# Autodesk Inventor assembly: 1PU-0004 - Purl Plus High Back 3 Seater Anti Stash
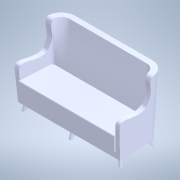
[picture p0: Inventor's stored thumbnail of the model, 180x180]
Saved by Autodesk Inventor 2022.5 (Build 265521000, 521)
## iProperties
Created: 2025-09
Part Number: 1PU-0004 - Purl Plus High Back 3 Seater Anti Stash
Description: STEP AP214
Document SubType Name: Assembly
Designer: Mark.Glazzard
Title: 1PU-0004 - Purl Plus High Back 3 Seater Anti Stash (UPHOLSTERED).STEP
Revision Number: ANY
Sending System: SolidWorks 2025
Preprocessor: SwSTEP 2.0
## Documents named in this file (5)
- S:\DRAWINGS\DRAWING OFFICE ONLY\WIP\1306 Purl 3-Seater\1PU-0004 - Purl Plus High Back 3-Seater Anti-Stash\1PU-0004 - SIMPLIFIED\1PU-0004 - Purl Plus High Back 3 Seater Anti Stash.iam
- S:\DRAWINGS\DRAWING OFFICE ONLY\WIP\1306 Purl 3-Seater\1PU-0004 - Purl Plus High Back 3-Seater Anti-Stash\1PU-0004 - STEP SAT DWG\1PU-0004 - BEECH FEET.ipt
- S:\DRAWINGS\DRAWING OFFICE ONLY\WIP\1306 Purl 3-Seater\1PU-0004 - Purl Plus High Back 3-Seater Anti-Stash\1PU-0004 - STEP SAT DWG\1PU-0004 - FR BLACK LINING FABRIC - 2SEATER.ipt
- S:\DRAWINGS\DRAWING OFFICE ONLY\WIP\1306 Purl 3-Seater\1PU-0004 - Purl Plus High Back 3-Seater Anti-Stash\1PU-0004 - STEP SAT DWG\1PU-0004 - Upholstery 2.ipt
- S:\DRAWINGS\DRAWING OFFICE ONLY\WIP\1306 Purl 3-Seater\1PU-0004 - Purl Plus High Back 3-Seater Anti-Stash\1PU-0004 - STEP SAT DWG\1PU-0004 - Upholstery 1.ipt
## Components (9 placed, 9 different names)
1. 1PU-0004 - BEECH FEET_1
2. 1PU-0004 - BEECH FEET_2
3. 1PU-0004 - BEECH FEET_3
4. 1PU-0004 - BEECH FEET_4
5. 1PU-0004 - FR BLACK LINING FABRIC - 2SEATER_5
6. 1PU-0004 - Upholstery 2_6
7. 1PU-0004 - Upholstery 1_7
8. 1PU-0004 - BEECH FEET_8
9. 1PU-0004 - BEECH FEET_9
